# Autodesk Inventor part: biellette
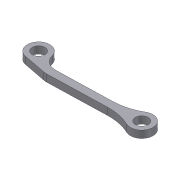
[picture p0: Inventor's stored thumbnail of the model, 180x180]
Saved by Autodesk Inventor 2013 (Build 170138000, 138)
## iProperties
Created: 2011-07
Part Number: biellette
Document SubType Name: Modeling
Designer: Laur
Density: 7.85 g/cm^3
Material: Acier allié
Mass: 1.60439 g
Surface Area: 4.18721 cm^2
Volume: 0.204381 cm^3
Author: Laur
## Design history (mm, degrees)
sketch "Esquisse1"
  geometry: L1 (21.191, -119.315)-(77.427, -119.427); L2 (77.427, -119.427)-(77.337, -164.658); L3 (77.337, -164.658)-(21.101, -164.546); L4 (21.101, -164.546)-(21.191, -119.315); L5 (25.447, -163.965)-(75.444, -163.428); L6 (42.012, -137.241)-(57.461, -136.823); L7 (41.744, -139.349)-(58.039, -138.908); L8 (34.517, -138.047)-(40.876, -139.278); C1 r 1.78 at (35.106, -135.004); C2 r 1.78 at (66.106, -137.504); A1 r 3.1 centre (35.106, -135.004) between (38.118, -134.268) and (34.517, -138.047); A2 r 3.1 centre (66.106, -137.504) between (64.793, -140.312) and (64.556, -134.819); A3 r 3.9 centre (41.906, -133.342) between (38.118, -134.268) and (42.012, -137.241); A4 r 4 centre (41.636, -135.35) between (40.876, -139.278) and (41.744, -139.349); A5 r 15 centre (58.445, -153.903) between (64.793, -140.312) and (58.039, -138.908); A6 r 15 centre (57.056, -121.829) between (57.461, -136.823) and (64.556, -134.819); 1 further point; 1 other entity
  constraints: 12 point on circle, 9 tangent, 8 centre point, 8 end point, 2 coincident, 2 point on line, 1 parallel, 3 other
  dimensions: "d32" = 50 distance of L5.start L5.end; "d82" = 3.56 diameter of C1; "d83" = 3.56 diameter of C2 (= d82); "d84" = 6.2 diameter of A1; "d85" = 6.2 diameter of A2 (= d84); "d86" = 2.1 distance between parallel lines of L7 L6; "d87" = 7.8 diameter of A3; "d88" = 6.8 horizontal distance of A3.centre C1.centre; "d89" = 167.5 deg angle of L7 L8; "d90" = 6.2 horizontal distance of point (41.306, -139.361) A1.centre; "d91" = 4 radius of A4; "d92" = 30 diameter of A5; "d96" = 30 diameter of A6 (= d92); "d110" = 31.1 distance of C2.centre C1.centre; "d111" = 2.5 vertical distance of A2.centre C1.centre
extrude "formes dont Ø3,56" new body sketch "Esquisse1" distance "d100" = 2; taper "d101" = 0 deg
sketch "Esquisse3"
  geometry: L1 (42.012, -137.241)-(57.461, -136.823) reference; L2 (40.876, -139.278)-(34.517, -138.047) reference; L3 (58.039, -138.908)-(41.744, -139.349) reference; C1 r 1.78 at (66.106, -137.504) reference; C2 r 1.78 at (35.106, -135.004) reference; A1 r 15 centre (57.056, -121.829) between (57.461, -136.823) and (64.556, -134.819) reference; A2 r 3.9 centre (41.906, -133.342) between (38.118, -134.268) and (42.012, -137.241) reference; A3 r 3.1 centre (35.106, -135.004) between (38.118, -134.268) and (34.517, -138.047) reference; A4 r 4 centre (41.636, -135.35) between (40.876, -139.278) and (41.744, -139.349) reference; A5 r 15 centre (58.445, -153.903) between (64.793, -140.312) and (58.039, -138.908) reference; A6 r 3.1 centre (66.106, -137.504) between (64.793, -140.312) and (64.556, -134.819) reference
node "Axe de construction1"
node "Solide1"
node "Corps solides"
node "Corps surfaciques"
node "Image2"
other parameters: "d114" = 60000, "sa_eq_min" = 13485.7, "sa_eq_max" = 1.28976e+07, "sa_pmax_min" = -386809, "sa_pmax_max" = 9999680, "sa_pmin_min" = -1.3015e+07, "sa_pmin_max" = 306964, "sa_d_min" = 0, "sa_d_max" = 0.12352, "sa_sf_min" = 19.3835
